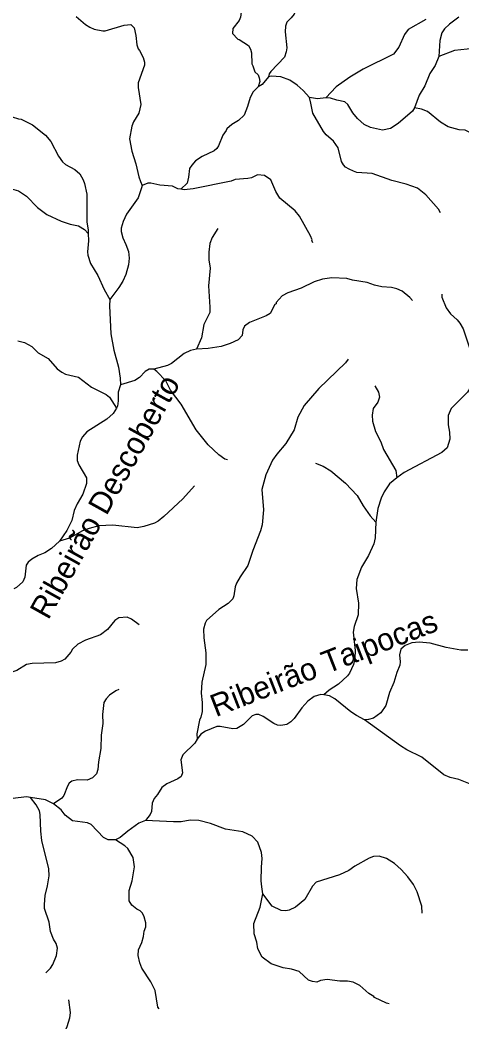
# Model space of a CAD drawing. Extents: x 500 to 555.2, y 9115.7 to 9171.
# Drawn here: x 539.23 to 543.19, y 9126.76 to 9135.74 of the extents above; entities that cross this region are included whole.
import ezdxf
from ezdxf.enums import TextEntityAlignment as Align

# ---------------------------------------------------------------- set-up
doc = ezdxf.new("R2010")
doc.units = 0
doc.header["$LTSCALE"] = 0.064
doc.layers.add('61', color=7, linetype='Continuous')
doc.layers.add('7', color=7, linetype='Continuous', lineweight=25)

msp = doc.modelspace()

# ---------------------------------------------------------------- linework, layer by layer
at = {"layer": '7'}
for points in [[(541.0493, 9136.237), (541.0888, 9136.1675), (541.0987, 9136.0847), (541.0955, 9135.9921), (541.105, 9135.9425), (541.1775, 9135.8642), (541.2101, 9135.8131), (541.2038, 9135.7665), (541.1903, 9135.7387), (541.1335, 9135.6671), (541.1318, 9135.6199), (541.1781, 9135.5699), (541.191, 9135.5685), (541.2738, 9135.5133), (541.2932, 9135.4818), (541.3022, 9135.447), (541.3054, 9135.3498), (541.3125, 9135.3307), (541.3321, 9135.2786), (541.3617, 9135.251), (541.3709, 9135.2245), (541.3756, 9135.19), (541.3614, 9135.1437)], [(541.944, 9136.2396), (541.9159, 9136.2009), (541.8817, 9136.0861), (541.8502, 9136.0518), (541.7253, 9135.9653), (541.7058, 9135.901), (541.6974, 9135.8282), (541.6839, 9135.7948), (541.6575, 9135.7605), (541.6176, 9135.7218), (541.6074, 9135.6859), (541.6024, 9135.6372), (541.6186, 9135.4929), (541.6138, 9135.4575), (541.598, 9135.4084), (541.4738, 9135.2804), (541.4614, 9135.2605), (541.4548, 9135.233)], [(539.7303, 9135.7729), (539.8156, 9135.7016), (539.8523, 9135.6773), (539.8909, 9135.6611), (539.9703, 9135.6444), (539.9912, 9135.6447), (540.1606, 9135.6968), (540.2206, 9135.7008), (540.2495, 9135.6708), (540.2654, 9135.6024), (540.273, 9135.5201), (540.2853, 9135.4838), (540.298, 9135.4698), (540.3308, 9135.4056), (540.3442, 9135.3649), (540.344, 9135.3378), (540.2852, 9135.1778), (540.2856, 9135.1363), (540.3113, 9134.9851), (540.2919, 9134.9071), (540.2446, 9134.8281), (540.23, 9134.7898), (540.2083, 9134.6773), (540.2309, 9134.5658), (540.2655, 9134.4535), (540.2933, 9134.3361), (540.3085, 9134.2955), (540.3218, 9134.2582)], [(543.1611, 9135.7662), (543.0766, 9135.7063), (543.0328, 9135.6629), (543.0092, 9135.6265), (542.9913, 9135.5598), (542.9797, 9135.4137)], [(542.8643, 9135.7481), (542.7052, 9135.6578), (542.6728, 9135.612), (542.623, 9135.4996), (542.5738, 9135.4368), (542.3022, 9135.3029), (542.1834, 9135.2302), (542.0611, 9135.1418), (541.967, 9135.0436)], [(544.0468, 9135.1205), (544.0432, 9135.2043), (544.034, 9135.2357), (544.0024, 9135.2863), (543.9443, 9135.3272), (543.8886, 9135.3407), (543.8047, 9135.3427), (543.7425, 9135.3597), (543.4631, 9135.4683), (543.3583, 9135.487), (543.2363, 9135.4819), (543.1211, 9135.4691), (542.9797, 9135.4137)], [(542.9797, 9135.4137), (542.947, 9135.3355), (542.8996, 9135.2632), (542.8551, 9135.1518), (542.804, 9135.0686), (542.7624, 9134.9542)], [(541.4548, 9135.233), (541.4543, 9135.2329), (541.3963, 9135.1629), (541.3614, 9135.1437)], [(541.823, 9135.0473), (541.7663, 9135.1096), (541.7123, 9135.1582), (541.6466, 9135.2015), (541.5653, 9135.2324), (541.4801, 9135.2387), (541.4548, 9135.233)], [(541.3614, 9135.1437), (541.3173, 9135.0986), (541.2891, 9135.0473), (541.2658, 9134.968)], [(541.967, 9135.0436), (541.8927, 9135.0344), (541.823, 9135.0473)], [(542.9971, 9134.0152), (542.9793, 9134.046), (542.8653, 9134.1747), (542.7902, 9134.236), (542.6878, 9134.2695), (542.5582, 9134.3034), (542.3848, 9134.3666), (542.2471, 9134.3749), (542.2155, 9134.3875), (542.1786, 9134.4041), (542.1457, 9134.4246), (542.1259, 9134.4455), (542.1096, 9134.4737), (542.0795, 9134.5978), (542.0354, 9134.6553), (541.9703, 9134.7139), (541.9469, 9134.7432), (541.8522, 9134.9071), (541.8338, 9134.9975), (541.823, 9135.0473)], [(542.7624, 9134.9542), (542.7623, 9134.9539), (542.7438, 9134.9254), (542.6162, 9134.8136), (542.548, 9134.7686), (542.4773, 9134.7554), (542.3672, 9134.7774), (542.313, 9134.8054), (542.2521, 9134.8584), (542.2112, 9134.9095), (542.1661, 9134.9858), (542.1375, 9135.0093), (542.0676, 9135.0243), (542.0094, 9135.0403), (541.967, 9135.0436)], [(541.2658, 9134.968), (541.2348, 9134.8885), (541.184, 9134.8424), (541.1256, 9134.8049), (541.0796, 9134.7655), (541.0755, 9134.7519), (541.0447, 9134.7094), (541.0072, 9134.6149), (540.992, 9134.5914), (540.9663, 9134.5695), (540.8599, 9134.52), (540.8014, 9134.4794), (540.7659, 9134.4403), (540.7476, 9134.411), (540.7379, 9134.3323), (540.7241, 9134.2791), (540.6685, 9134.2267)], [(543.8736, 9134.8869), (543.7954, 9134.8325), (543.7064, 9134.8075), (543.6447, 9134.7606), (543.6242, 9134.7538), (543.5724, 9134.7537), (543.5201, 9134.7453), (543.4432, 9134.7052), (543.363, 9134.6964), (543.3046, 9134.7123), (543.2167, 9134.7534), (543.1636, 9134.7584), (543.0644, 9134.7847), (542.9966, 9134.8276), (542.8795, 9134.9236), (542.827, 9134.9441), (542.7624, 9134.9542)], [(538.9427, 9134.9397), (539.0113, 9134.9054), (539.1555, 9134.8753), (539.2137, 9134.8553), (539.2387, 9134.852), (539.3404, 9134.8029), (539.4562, 9134.7114), (539.5028, 9134.6536), (539.5724, 9134.5217), (539.6094, 9134.47), (539.6362, 9134.4467), (539.7191, 9134.4031), (539.7643, 9134.363), (539.7939, 9134.3102), (539.805, 9134.2782), (539.8259, 9134.1813), (539.826, 9133.9313), (539.8371, 9133.8603), (539.8382, 9133.8296)], [(541.8516, 9133.7439), (541.8434, 9133.7671), (541.8462, 9133.7734), (541.832, 9133.8073), (541.7311, 9133.9855), (541.6932, 9134.0313), (541.5566, 9134.1443), (541.5215, 9134.2054), (541.4743, 9134.3106), (541.4181, 9134.3498), (541.3556, 9134.3534), (541.3022, 9134.3289), (541.2677, 9134.3211), (541.1566, 9134.3122), (541.121, 9134.2976), (540.7788, 9134.2291), (540.6982, 9134.2203), (540.6685, 9134.2267)], [(538.9732, 9134.1962), (539.0751, 9134.2272), (539.1513, 9134.2286), (539.2138, 9134.2115), (539.2856, 9134.1624), (539.3826, 9134.0605), (539.4678, 9134.0002), (539.5965, 9133.9378), (539.6755, 9133.9126), (539.7525, 9133.898), (539.8057, 9133.8632), (539.8382, 9133.8296)], [(540.3218, 9134.2582), (540.316, 9134.2368), (540.2868, 9134.1484), (540.1803, 9134.0008), (540.1513, 9133.9366), (540.1344, 9133.8769), (540.1343, 9133.8467), (540.1482, 9133.7901), (540.1767, 9133.7291), (540.1982, 9133.6662), (540.2048, 9133.6079), (540.1999, 9133.5488), (540.1771, 9133.4602), (540.1493, 9133.4011), (540.1138, 9133.3443), (540.033, 9133.2377)], [(540.6685, 9134.2267), (540.668, 9134.2262), (540.6412, 9134.229), (540.5952, 9134.252), (540.4794, 9134.2632), (540.4, 9134.2796), (540.3715, 9134.2792), (540.3218, 9134.2582)], [(541.0002, 9133.8736), (540.9504, 9133.7935), (540.9299, 9133.7384), (540.9185, 9133.6602), (540.9184, 9133.5935), (540.9315, 9133.5193), (540.9168, 9133.3611), (540.9297, 9133.1683), (540.9281, 9133.1213), (540.876, 9133.014), (540.8525, 9132.8932), (540.8099, 9132.7918)], [(539.8382, 9133.8296), (539.8407, 9133.7628), (539.8325, 9133.6643), (539.8363, 9133.6343), (539.8601, 9133.5585), (539.924, 9133.4535), (539.9809, 9133.3266), (540.033, 9133.2377)], [(542.7442, 9133.2281), (542.7217, 9133.2554), (542.6527, 9133.3109), (542.6041, 9133.3333), (542.5559, 9133.3461), (542.4692, 9133.352), (542.405, 9133.3659), (542.3373, 9133.3905), (542.2083, 9133.4103), (542.1564, 9133.4253), (542.0207, 9133.43), (541.9369, 9133.4187), (541.8631, 9133.3955), (541.7457, 9133.3384), (541.6285, 9133.2977), (541.5762, 9133.2707), (541.5231, 9133.2115), (541.5216, 9133.1989), (541.5123, 9133.192), (541.4681, 9133.1126), (541.4327, 9133.0919), (541.2832, 9133.03), (541.239, 9132.9975), (541.2236, 9132.9642), (541.2169, 9132.9139), (541.1826, 9132.8766), (541.1093, 9132.843), (541.0293, 9132.8164), (540.9125, 9132.7969), (540.8099, 9132.7918)], [(543.0083, 9133.2861), (543.0088, 9133.2572), (543.0462, 9133.1638), (543.0864, 9133.109), (543.1458, 9133.0544), (543.1701, 9133.0237), (543.1985, 9132.9734), (543.2526, 9132.8119), (543.2932, 9132.6179), (543.287, 9132.5261), (543.256, 9132.4366), (543.238, 9132.4071), (543.0925, 9132.2613), (543.0642, 9132.1984), (543.0655, 9132.1152), (543.077, 9132.0483), (543.0802, 9131.984), (543.0571, 9131.9079), (543.0075, 9131.8672), (542.6708, 9131.6867), (542.6033, 9131.6395)], [(540.033, 9133.2377), (540.0282, 9133.1812), (540.0427, 9132.93), (540.069, 9132.7823), (540.1113, 9132.6295), (540.1261, 9132.5311), (540.1267, 9132.4716)], [(539.2078, 9132.866), (539.2676, 9132.8512), (539.3338, 9132.8149), (539.3904, 9132.7602), (539.4786, 9132.7074), (539.5602, 9132.6165), (539.6013, 9132.5853), (539.6339, 9132.5684), (539.7511, 9132.5422), (539.8693, 9132.4521), (539.9998, 9132.3851), (540.0279, 9132.3618), (540.0908, 9132.2643)], [(540.8099, 9132.7918), (540.7547, 9132.7786), (540.6977, 9132.7522), (540.5837, 9132.6641), (540.5491, 9132.6451), (540.4255, 9132.614)], [(542.1697, 9132.703), (542.1443, 9132.6681), (541.9055, 9132.4388), (541.7742, 9132.2878), (541.7186, 9132.1829), (541.6837, 9132.0676), (541.6088, 9131.9456), (541.5281, 9131.8512), (541.4906, 9131.7974), (541.4304, 9131.6657), (541.3944, 9131.5352), (541.4104, 9131.3508), (541.3986, 9131.2175), (541.3833, 9131.164), (541.3134, 9130.9866), (541.2677, 9130.8516), (541.1989, 9130.7514), (541.1675, 9130.695), (541.1565, 9130.6619), (541.1445, 9130.5819), (541.1338, 9130.5549), (541.0927, 9130.5136), (541.0081, 9130.4602), (540.8992, 9130.3598), (540.8867, 9130.3351), (540.8725, 9130.2825), (540.8757, 9130.2059), (540.8921, 9130.0707), (540.8936, 9129.9651), (540.856, 9129.8076), (540.8494, 9129.7092), (540.8592, 9129.6259), (540.8592, 9129.5458), (540.8482, 9129.4947), (540.8361, 9129.4657), (540.8111, 9129.3454), (540.8146, 9129.298)], [(540.4255, 9132.614), (540.3861, 9132.6126), (540.3479, 9132.5921), (540.2982, 9132.5377), (540.2573, 9132.5099), (540.1267, 9132.4716)], [(541.0861, 9131.8005), (541.0619, 9131.8073), (541.009, 9131.8444), (540.9139, 9131.9353), (540.8069, 9132.0703), (540.6722, 9132.2991), (540.5765, 9132.4256), (540.5351, 9132.5073), (540.454, 9132.5918), (540.4255, 9132.614)], [(540.1267, 9132.4716), (540.1084, 9132.4081), (540.108, 9132.3277), (540.0997, 9132.2806), (540.0908, 9132.2643)], [(542.4065, 9132.462), (542.4397, 9132.4078), (542.4487, 9132.3611), (542.4343, 9132.3172), (542.393, 9132.2597), (542.3848, 9132.2008), (542.3879, 9132.1479), (542.4138, 9132.0535), (542.4599, 9131.961), (542.4853, 9131.8938), (542.5944, 9131.7033), (542.6033, 9131.6395)], [(540.0908, 9132.2643), (540.0608, 9132.2146), (540.0048, 9132.1651), (539.8271, 9132.0514), (539.7881, 9132.0068), (539.7669, 9131.9669), (539.7395, 9131.8424), (539.7385, 9131.7939), (539.7539, 9131.7539), (539.8224, 9131.6401), (539.8236, 9131.5885), (539.7906, 9131.4929), (539.7388, 9131.4053), (539.7139, 9131.3454), (539.6911, 9131.2578), (539.6473, 9131.1673), (539.5826, 9131.0706)], [(541.8769, 9131.7716), (541.9444, 9131.7426), (542.014, 9131.7011), (542.143, 9131.5903), (542.2493, 9131.4803), (542.3017, 9131.3878), (542.3654, 9131.2971), (542.4148, 9131.2401)], [(542.6033, 9131.6395), (542.5392, 9131.5863), (542.4912, 9131.5135), (542.4635, 9131.4551), (542.4354, 9131.3651), (542.4148, 9131.2401)], [(540.7913, 9131.5667), (540.6854, 9131.4502), (540.5164, 9131.2912), (540.4668, 9131.2515), (540.4329, 9131.232), (540.3371, 9131.2023), (540.278, 9131.1911), (540.0588, 9131.2156), (539.9336, 9131.2088), (539.8456, 9131.186), (539.7879, 9131.1637), (539.6698, 9131.0966), (539.5826, 9131.0706)], [(542.4148, 9131.2401), (542.4109, 9131.1008), (542.3976, 9131.0477), (542.3506, 9130.9439), (542.2878, 9130.8384), (542.2469, 9130.7262), (542.239, 9130.6467), (542.2601, 9130.5168), (542.2565, 9130.4105), (542.2224, 9130.3069), (542.2142, 9130.2551), (542.2306, 9130.091), (542.2273, 9130.0196), (542.2173, 9129.9658), (542.18, 9129.8876), (542.1637, 9129.8647), (542.0818, 9129.791), (541.9988, 9129.7353), (541.9505, 9129.6952)], [(539.5826, 9131.0706), (539.5098, 9131.0041), (539.45, 9130.967), (539.3897, 9130.9417), (539.3344, 9130.9108), (539.2997, 9130.8833), (539.2825, 9130.8555), (539.2696, 9130.7492), (539.2511, 9130.7061), (539.1967, 9130.6569), (539.171, 9130.6451)], [(540.2944, 9130.322), (540.2257, 9130.3734), (540.1888, 9130.3898), (540.1126, 9130.3837), (540.0775, 9130.3614), (540.0112, 9130.2806), (539.9478, 9130.2318), (539.8156, 9130.1853), (539.744, 9130.1478), (539.6974, 9130.103), (539.6829, 9130.0752), (539.6285, 9130.0147), (539.5951, 9129.9955), (539.5444, 9129.9809), (539.3372, 9129.9739), (539.2866, 9129.9661), (539.1993, 9129.9133), (539.0993, 9129.88)], [(543.2419, 9130.0938), (543.1794, 9130.0953), (543.0476, 9130.1194), (542.9025, 9130.1559), (542.8054, 9130.1674), (542.7398, 9130.1594), (542.6795, 9130.1375), (542.6408, 9130.1034), (542.6294, 9130.0517), (542.634, 9129.9894), (542.6307, 9129.9593), (542.6051, 9129.895), (542.5778, 9129.8036), (542.5381, 9129.7139), (542.506, 9129.5984), (542.4613, 9129.5339), (542.3961, 9129.4836), (542.3519, 9129.4732), (542.3153, 9129.4705)], [(540.1124, 9129.7411), (540.0861, 9129.7301), (540.0294, 9129.6901), (540.0003, 9129.6591), (539.9784, 9129.624), (539.9654, 9129.5163), (539.9702, 9129.4375), (539.9539, 9129.3321), (539.9504, 9129.2134), (539.9311, 9129.0938), (539.9258, 9129.0232), (539.9114, 9128.987), (539.8772, 9128.9495), (539.8287, 9128.9289), (539.7439, 9128.9322), (539.6917, 9128.9191), (539.6686, 9128.9011), (539.6525, 9128.8753), (539.6194, 9128.792), (539.6008, 9128.7679), (539.5282, 9128.7179)], [(541.9505, 9129.6952), (541.9236, 9129.6982), (541.8645, 9129.6792), (541.8079, 9129.6362), (541.7545, 9129.5781), (541.6832, 9129.4807), (541.6535, 9129.4514), (541.6193, 9129.4282), (541.5653, 9129.4179), (541.5345, 9129.4231), (541.5019, 9129.4365), (541.4065, 9129.5001), (541.3678, 9129.5177), (541.3409, 9129.5164), (541.3093, 9129.5067), (541.2288, 9129.4268), (541.1709, 9129.3918), (541.1355, 9129.3886), (541.0215, 9129.4094), (540.9912, 9129.4097), (540.8909, 9129.368), (540.8488, 9129.3419), (540.8146, 9129.298)], [(542.0501, 9129.659), (542.0007, 9129.6835), (541.9505, 9129.6952)], [(542.3153, 9129.4705), (542.2427, 9129.5079), (542.1923, 9129.5414), (542.0501, 9129.659)], [(543.6012, 9128.1295), (543.5648, 9128.1932), (543.5431, 9128.2456), (543.5363, 9128.2987), (543.5098, 9128.406), (543.4969, 9128.5316), (543.4737, 9128.6705), (543.4445, 9128.7481), (543.4119, 9128.7941), (543.3338, 9128.8561), (543.2799, 9128.8866), (543.1615, 9128.9343), (543.0829, 9128.9523), (543.0262, 9128.9783), (542.8282, 9129.1353), (542.6942, 9129.201), (542.6371, 9129.2365), (542.3153, 9129.4705)], [(540.8146, 9129.298), (540.7949, 9129.2606), (540.6877, 9129.1575), (540.6691, 9129.1113), (540.6836, 9128.995), (540.6724, 9128.9624), (540.6421, 9128.9402), (540.5439, 9128.8974), (540.4989, 9128.8638), (540.46, 9128.7993), (540.4293, 9128.7644), (540.4117, 9128.7224), (540.4048, 9128.6491), (540.3933, 9128.6208), (540.3517, 9128.5685)], [(539.3205, 9128.774), (539.2854, 9128.7793), (539.1618, 9128.7646), (539.0732, 9128.7353), (538.9107, 9128.719), (538.8404, 9128.6826), (538.8184, 9128.682), (538.7951, 9128.6848), (538.7944, 9128.6855)], [(539.4596, 9127.2019), (539.4994, 9127.2429), (539.5226, 9127.2778), (539.5551, 9127.3578), (539.5633, 9127.4245), (539.5522, 9127.4654), (539.5274, 9127.5051), (539.4999, 9127.5737), (539.4881, 9127.6557), (539.448, 9127.779), (539.4454, 9127.8143), (539.4518, 9127.8945), (539.4732, 9127.981), (539.4879, 9128.0702), (539.4842, 9128.1345), (539.4221, 9128.3871), (539.4126, 9128.4725), (539.4091, 9128.6214), (539.4021, 9128.6531), (539.3723, 9128.708), (539.3205, 9128.774)], [(539.5282, 9128.7179), (539.4562, 9128.7535), (539.3205, 9128.774)], [(540.0829, 9128.3946), (540.017, 9128.3944), (539.9769, 9128.4157), (539.8653, 9128.5303), (539.8307, 9128.5478), (539.6975, 9128.5654), (539.6309, 9128.6159), (539.5953, 9128.6641), (539.5282, 9128.7179)], [(540.3517, 9128.5685), (540.293, 9128.5432), (540.1933, 9128.473), (540.1234, 9128.4156), (540.0829, 9128.3946)], [(541.4037, 9127.9109), (541.3933, 9127.9728), (541.3874, 9128.0265), (541.3908, 9128.149), (541.3988, 9128.2277), (541.3906, 9128.2802), (541.3576, 9128.3744), (541.3091, 9128.4266), (541.2241, 9128.4646), (541.0685, 9128.4888), (540.9347, 9128.5403), (540.8292, 9128.5681), (540.751, 9128.5714), (540.6723, 9128.5568), (540.6021, 9128.555), (540.3517, 9128.5685)], [(540.4741, 9126.8791), (540.4632, 9126.895), (540.4386, 9127.0448), (540.4009, 9127.1227), (540.3197, 9127.2429), (540.3, 9127.2921), (540.2856, 9127.3565), (540.2904, 9127.4075), (540.3182, 9127.4731), (540.3341, 9127.5271), (540.3389, 9127.5753), (540.3538, 9127.6156), (540.3557, 9127.6497), (540.3409, 9127.7054), (540.3245, 9127.7363), (540.3031, 9127.7594), (540.2755, 9127.7727), (540.2303, 9127.8096), (540.2065, 9127.8473), (540.2067, 9127.9398), (540.2329, 9128.0276), (540.2539, 9128.151), (540.2424, 9128.2352), (540.1922, 9128.3167), (540.167, 9128.3402), (540.125, 9128.3662), (540.0829, 9128.3946)], [(542.8316, 9127.7381), (542.8292, 9127.8011), (542.7864, 9127.9289), (542.7531, 9127.9951), (542.7035, 9128.0639), (542.6435, 9128.1273), (542.5832, 9128.181), (542.5105, 9128.2281), (542.445, 9128.2466), (542.3952, 9128.2435), (542.3553, 9128.2302), (542.2293, 9128.1573), (542.1748, 9128.1188), (542.0909, 9128.0799), (541.8829, 9128.0153), (541.8479, 9127.9779), (541.7791, 9127.8592), (541.6964, 9127.7895), (541.6395, 9127.7628), (541.6099, 9127.7579), (541.5674, 9127.7599), (541.4871, 9127.7996), (541.4037, 9127.9109)], [(542.5362, 9126.9242), (542.5108, 9126.9291), (542.4051, 9126.9802), (542.3994, 9126.99), (542.3546, 9127.0174), (542.2727, 9127.089), (542.2136, 9127.1182), (542.1617, 9127.1264), (542.0935, 9127.1267), (541.9792, 9127.1427), (541.919, 9127.1344), (541.8861, 9127.1185), (541.8501, 9127.1232), (541.8127, 9127.1373), (541.7304, 9127.2154), (541.6597, 9127.2362), (541.587, 9127.2463), (541.4788, 9127.2842), (541.3978, 9127.3426), (541.3581, 9127.4185), (541.3483, 9127.4784), (541.3251, 9127.5519), (541.3219, 9127.6433), (541.3795, 9127.7914), (541.4037, 9127.9109)], [(539.6624, 9126.9595), (539.6766, 9126.8459), (539.6717, 9126.7967), (539.6473, 9126.7185), (539.5551, 9126.5205), (539.5471, 9126.4543), (539.5618, 9126.3478), (539.5858, 9126.2971), (539.7299, 9126.1493), (539.7635, 9126.0996), (539.8457, 9125.9169), (539.8885, 9125.7595), (539.9421, 9125.6425), (539.9883, 9125.5238), (540.0112, 9125.432), (540.0094, 9125.3986), (539.9928, 9125.3384)]]:
    msp.add_lwpolyline(points, dxfattribs=at)

# ---------------------------------------------------------------- texts
at = {"layer": '61'}
for s, rotation, p in [('Ribeirão Descoberto', 60.832, (540.0744, 9131.4227)), ('Ribeirão Taipocas', 21.286, (541.9859, 9129.8843))]:
    msp.add_text(s, height=0.2, rotation=rotation, dxfattribs=at).set_placement(p, align=Align.CENTER)

doc.saveas('drawing.dxf')
